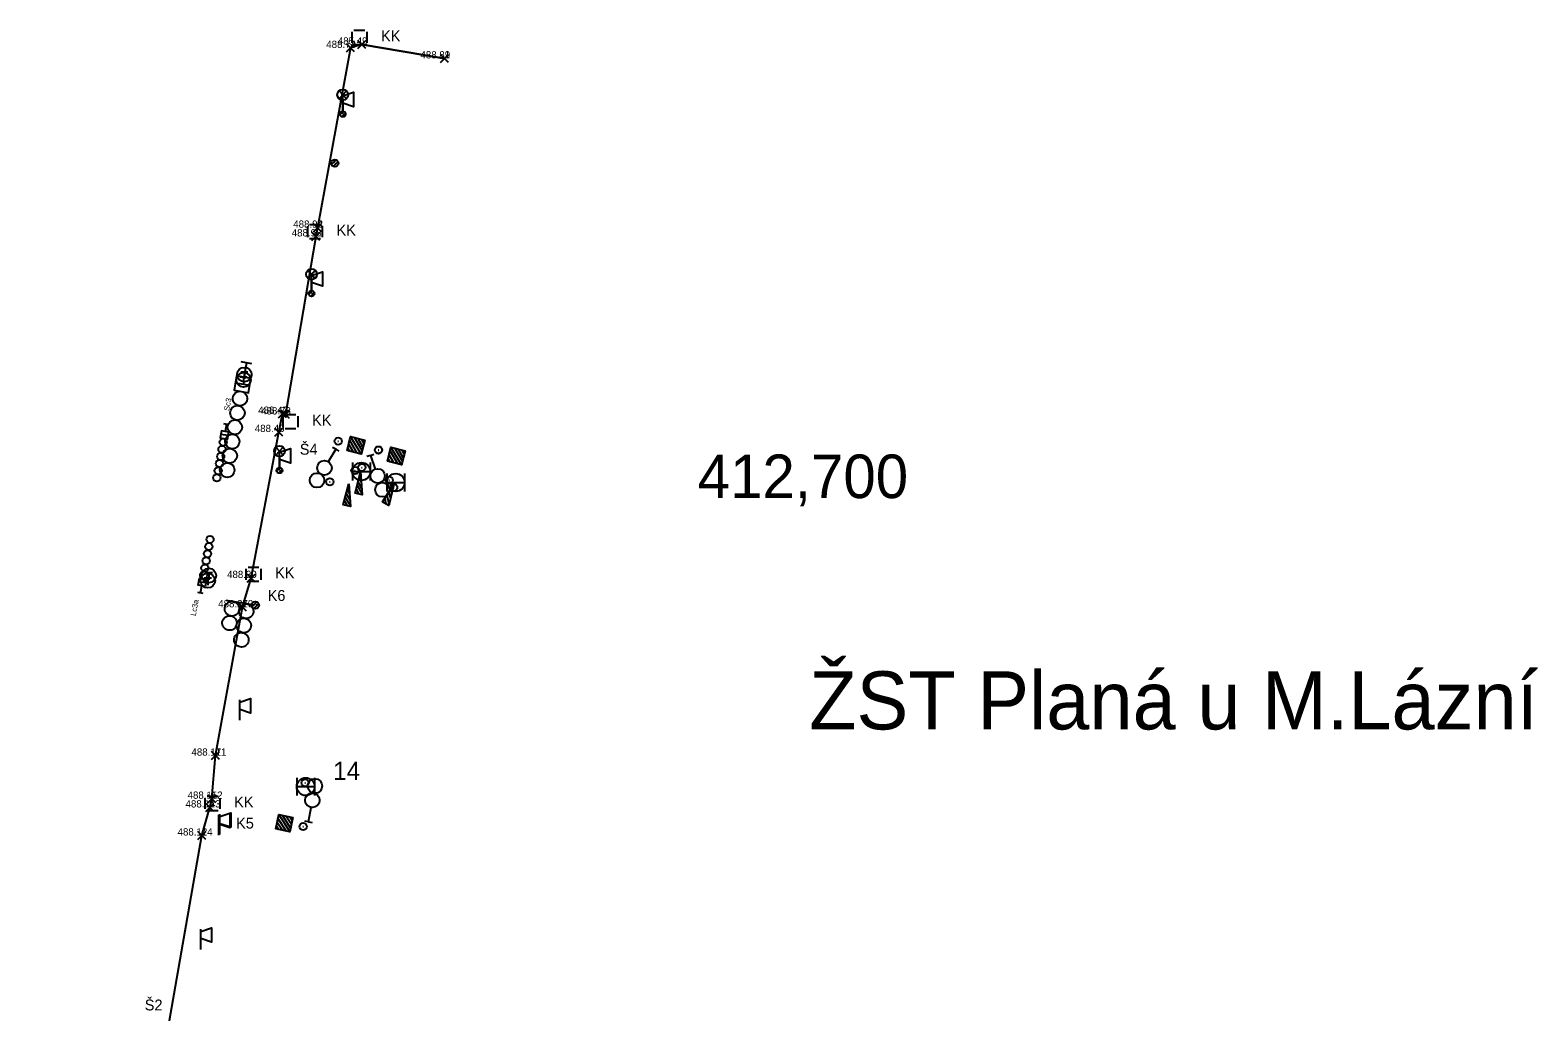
# Model space of a CAD drawing. Extents: x -874058 to -854960, y -10531873 to -1049126.
# Drawn here: x -866509.5 to -866301.7, y -1050024 to -1049888.8 of the extents above; entities that cross this region are included whole.
import ezdxf

# ---------------------------------------------------------------- set-up
doc = ezdxf.new("R2010")
doc.units = 0
for name, color, linetype in [('PS 63-21-01_Návěstidla', 7, 'Continuous'), ('PS 63-21-01_Názvy_náv', 7, 'Continuous'), ('SO_63-33-21_pedestrail', 7, 'Continuous'), ('Vrstva 2', 7, 'Continuous'), ('Vrstva 23', 7, 'Continuous'), ('Vrstva 25', 7, 'Continuous'), ('Vrstva 3', 7, 'Continuous'), ('Vrstva 31', 7, 'Continuous'), ('Vrstva 32', 7, 'Continuous'), ('Vrstva 33', 7, 'Continuous'), ('Vrstva 35', 7, 'Continuous'), ('Vrstva 36', 7, 'Continuous'), ('Vrstva 50', 7, 'Continuous'), ('Vrstva 6', 7, 'Continuous'), ('Vrstva 60', 7, 'Continuous'), ('Vrstva 61', 7, 'Continuous'), ('Vrstva 7', 7, 'Continuous')]:
    doc.layers.add(name, color=color, linetype=linetype)

msp = doc.modelspace()

# ---------------------------------------------------------------- linework, layer by layer
at = {"layer": 'PS 63-21-01_Návěstidla'}
for p, q in [((-866482.23, -1049944.59), (-866483.21, -1049944.42)), ((-866482.23, -1049944.59), (-866483.21, -1049944.42)), ((-866482.09, -1049943.1), (-866482.82, -1049942.96)), ((-866482.09, -1049943.1), (-866482.82, -1049942.96)), ((-866482.45, -1049943.03), (-866482.45, -1049943.03)), ((-866482.45, -1049943.03), (-866482.45, -1049943.03)), ((-866485.28, -1049964.89), (-866486.27, -1049964.71)), ((-866485.28, -1049964.89), (-866486.27, -1049964.71)), ((-866485.67, -1049966.34), (-866486.41, -1049966.21)), ((-866485.67, -1049966.34), (-866486.41, -1049966.21)), ((-866486.04, -1049966.27), (-866486.04, -1049966.27)), ((-866486.04, -1049966.27), (-866486.04, -1049966.27))]:
    msp.add_line(p, q, dxfattribs=at)
for points in [[(-866482.45, -1049943.03), (-866482.63, -1049944.01), (-866483.12, -1049943.93), (-866483.3, -1049944.91), (-866482.32, -1049945.09), (-866482.14, -1049944.1), (-866482.63, -1049944.01)], [(-866482.45, -1049943.03), (-866482.63, -1049944.01), (-866483.12, -1049943.93), (-866483.3, -1049944.91), (-866482.32, -1049945.09), (-866482.14, -1049944.1), (-866482.63, -1049944.01)], [(-866486.04, -1049966.27), (-866485.86, -1049965.29), (-866486.36, -1049965.2), (-866486.18, -1049964.22), (-866485.2, -1049964.39), (-866485.37, -1049965.38), (-866485.86, -1049965.29)], [(-866486.04, -1049966.27), (-866485.86, -1049965.29), (-866486.36, -1049965.2), (-866486.18, -1049964.22), (-866485.2, -1049964.39), (-866485.37, -1049965.38), (-866485.86, -1049965.29)]]:
    msp.add_lwpolyline(points, dxfattribs=at)
for centre in [(-866483.07, -1049946.48), (-866483.07, -1049946.48), (-866482.9, -1049945.49), (-866482.9, -1049945.49), (-866483.42, -1049948.44), (-866483.42, -1049948.44), (-866483.25, -1049947.46), (-866483.25, -1049947.46), (-866483.78, -1049950.41), (-866483.78, -1049950.41), (-866483.6, -1049949.43), (-866483.6, -1049949.43), (-866484.72, -1049958.89), (-866484.72, -1049958.89), (-866485.07, -1049960.86), (-866485.07, -1049960.86), (-866484.89, -1049959.88), (-866484.89, -1049959.88), (-866485.42, -1049962.83), (-866485.42, -1049962.83), (-866485.25, -1049961.84), (-866485.25, -1049961.84), (-866485.6, -1049963.81), (-866485.6, -1049963.81)]:
    msp.add_circle(centre, 0.5, dxfattribs=at)
at = {"layer": 'Vrstva 25'}
for p, q in [((-866466.92, -1049897.09), (-866465.93, -1049898.21)), ((-866466.91, -1049898.22), (-866465.93, -1049897.1)), ((-866466.43, -1049898.4), (-866466.43, -1049899.9)), ((-866466.82, -1049900.38), (-866466.35, -1049899.91)), ((-866466.55, -1049900.68), (-866466.05, -1049900.18)), ((-866471.22, -1049921.81), (-866470.23, -1049922.93)), ((-866471.21, -1049922.94), (-866470.22, -1049921.82)), ((-866470.73, -1049923.12), (-866470.73, -1049924.62)), ((-866471.12, -1049925.1), (-866470.65, -1049924.63)), ((-866470.85, -1049925.4), (-866470.35, -1049924.9)), ((-866475.64, -1049946.17), (-866474.65, -1049947.28)), ((-866475.63, -1049947.3), (-866474.65, -1049946.18)), ((-866475.15, -1049947.48), (-866475.15, -1049948.98)), ((-866475.54, -1049949.46), (-866475.07, -1049948.99)), ((-866475.27, -1049949.76), (-866474.77, -1049949.26))]:
    msp.add_line(p, q, dxfattribs=at)
for centre, radius in [((-866466.43, -1049897.65), 0.749), ((-866466.43, -1049900.3), 0.4), ((-866466.43, -1049900.3), 0.4), ((-866470.73, -1049922.37), 0.749), ((-866470.73, -1049925.02), 0.4), ((-866470.73, -1049925.02), 0.4), ((-866475.15, -1049946.73), 0.749), ((-866475.15, -1049949.38), 0.4), ((-866475.15, -1049949.38), 0.4)]:
    msp.add_circle(centre, radius, dxfattribs=at)
at = {"layer": 'Vrstva 3'}
for p, q in [((-866480.49, -1049935.79), (-866479.49, -1049935.79)), ((-866479.99, -1049935.79), (-866479.99, -1049936.79)), ((-866480.59, -1049936.51), (-866479.59, -1049936.51)), ((-866480.09, -1049936.51), (-866480.09, -1049937.51)), ((-866465.44, -1049946.76), (-866465.74, -1049946.26)), ((-866464.93, -1049946.89), (-866465.61, -1049945.75)), ((-866464.42, -1049947.03), (-866465.47, -1049945.24)), ((-866463.9, -1049947.16), (-866465.34, -1049944.72)), ((-866463.77, -1049946.65), (-866464.83, -1049944.85)), ((-866463.64, -1049946.13), (-866464.31, -1049944.99)), ((-866463.51, -1049945.62), (-866463.8, -1049945.12)), ((-866458.34, -1049948.63), (-866459.78, -1049946.19)), ((-866458.21, -1049948.12), (-866459.27, -1049946.32)), ((-866458.08, -1049947.6), (-866458.75, -1049946.46)), ((-866465.09, -1049948.31), (-866465.09, -1049950.77)), ((-866462.63, -1049948.31), (-866462.63, -1049950.77)), ((-866459.88, -1049948.23), (-866460.18, -1049947.73)), ((-866459.37, -1049948.36), (-866460.05, -1049947.22)), ((-866458.86, -1049948.5), (-866459.91, -1049946.71)), ((-866457.95, -1049947.09), (-866458.24, -1049946.59)), ((-866465.09, -1049949.54), (-866462.63, -1049949.54)), ((-866464.2, -1049950.44), (-866463.88, -1049950.97)), ((-866464.06, -1049949.93), (-866463.94, -1049950.14)), ((-866460.36, -1049949.82), (-866460.36, -1049952.28)), ((-866457.9, -1049949.82), (-866457.9, -1049952.28)), ((-866465.94, -1049952.57), (-866465.44, -1049953.42)), ((-866465.81, -1049952.06), (-866465.5, -1049952.58)), ((-866465.67, -1049951.54), (-866465.55, -1049951.75)), ((-866464.73, -1049952.49), (-866464.72, -1049952.51)), ((-866464.6, -1049951.98), (-866464.21, -1049952.64)), ((-866464.46, -1049951.47), (-866463.77, -1049952.64)), ((-866464.33, -1049950.95), (-866463.83, -1049951.81)), ((-866460.36, -1049951.05), (-866457.9, -1049951.05)), ((-866460.36, -1049952.79), (-866460.05, -1049954.12)), ((-866460.08, -1049952.34), (-866459.86, -1049953.3)), ((-866459.8, -1049951.89), (-866459.66, -1049952.49)), ((-866459.52, -1049951.44), (-866459.47, -1049951.67)), ((-866466.34, -1049954.11), (-866466.34, -1049954.12)), ((-866466.21, -1049953.59), (-866465.82, -1049954.25)), ((-866466.08, -1049953.08), (-866465.39, -1049954.26)), ((-866460.92, -1049953.69), (-866460.92, -1049953.7)), ((-866460.64, -1049953.24), (-866460.47, -1049953.99)), ((-866485.53, -1049964.17), (-866484.53, -1049964.17)), ((-866485.38, -1049963.46), (-866484.38, -1049963.46)), ((-866485.03, -1049964.17), (-866485.03, -1049965.17)), ((-866484.88, -1049963.46), (-866484.88, -1049964.46)), ((-866472.76, -1049991.71), (-866472.76, -1049994.17)), ((-866470.3, -1049991.71), (-866470.3, -1049994.17)), ((-866472.76, -1049992.94), (-866470.3, -1049992.94)), ((-866475.59, -1049998.35), (-866475.27, -1049998.83)), ((-866475.48, -1049997.83), (-866474.75, -1049998.94)), ((-866475.37, -1049997.31), (-866474.23, -1049999.05)), ((-866475.26, -1049996.79), (-866473.71, -1049999.16)), ((-866474.75, -1049996.9), (-866473.61, -1049998.64)), ((-866474.23, -1049997.01), (-866473.5, -1049998.12)), ((-866473.71, -1049997.12), (-866473.39, -1049997.6))]:
    msp.add_line(p, q, dxfattribs=at)
for points in [[(-866465.84, -1049946.66), (-866465.34, -1049944.72), (-866463.4, -1049945.22), (-866463.9, -1049947.16)], [(-866465.84, -1049946.66), (-866465.34, -1049944.72), (-866463.4, -1049945.22), (-866463.9, -1049947.16)], [(-866460.28, -1049948.13), (-866459.78, -1049946.19), (-866457.84, -1049946.69), (-866458.34, -1049948.63)], [(-866460.28, -1049948.13), (-866459.78, -1049946.19), (-866457.84, -1049946.69), (-866458.34, -1049948.63)], [(-866473.31, -1049997.2), (-866473.71, -1049999.16), (-866475.67, -1049998.75), (-866475.26, -1049996.79)], [(-866473.31, -1049997.2), (-866473.71, -1049999.16), (-866475.67, -1049998.75), (-866475.26, -1049996.79)]]:
    msp.add_lwpolyline(points, close=True, dxfattribs=at)
for points in [[(-866465.84, -1049946.66), (-866465.34, -1049944.72), (-866463.4, -1049945.22), (-866463.9, -1049947.16), (-866465.84, -1049946.66)], [(-866465.84, -1049946.66), (-866465.34, -1049944.72), (-866463.4, -1049945.22), (-866463.9, -1049947.16), (-866465.84, -1049946.66)], [(-866460.28, -1049948.13), (-866459.78, -1049946.19), (-866457.84, -1049946.69), (-866458.34, -1049948.63), (-866460.28, -1049948.13)], [(-866460.28, -1049948.13), (-866459.78, -1049946.19), (-866457.84, -1049946.69), (-866458.34, -1049948.63), (-866460.28, -1049948.13)], [(-866463.98, -1049949.6), (-866463.77, -1049952.76), (-866464.73, -1049952.5), (-866463.98, -1049949.6)], [(-866463.98, -1049949.6), (-866463.77, -1049952.76), (-866464.73, -1049952.5), (-866463.98, -1049949.6)], [(-866465.59, -1049951.22), (-866465.38, -1049954.37), (-866466.35, -1049954.12), (-866465.59, -1049951.22)], [(-866465.59, -1049951.22), (-866465.38, -1049954.37), (-866466.35, -1049954.12), (-866465.59, -1049951.22)], [(-866459.34, -1049951.15), (-866460.08, -1049954.23), (-866460.93, -1049953.7), (-866459.34, -1049951.15)], [(-866459.34, -1049951.15), (-866460.08, -1049954.23), (-866460.93, -1049953.7), (-866459.34, -1049951.15)], [(-866473.31, -1049997.2), (-866473.71, -1049999.16), (-866475.67, -1049998.75), (-866475.26, -1049996.79), (-866473.31, -1049997.2)], [(-866473.31, -1049997.2), (-866473.71, -1049999.16), (-866475.67, -1049998.75), (-866475.26, -1049996.79), (-866473.31, -1049997.2)]]:
    msp.add_lwpolyline(points, dxfattribs=at)
for centre, radius in [((-866480.09, -1049936.91), 1), ((-866479.99, -1049936.19), 1), ((-866463.86, -1049949.54), 1.23), ((-866459.13, -1049951.05), 1.23), ((-866484.88, -1049963.86), 1), ((-866485.03, -1049964.57), 1), ((-866471.53, -1049992.94), 1.23)]:
    msp.add_circle(centre, radius, dxfattribs=at)
at = {"layer": 'Vrstva 32'}
msp.add_line((-866470.13, -1049917.16), (-866474.34, -1049941.68), dxfattribs=at)
for points in [[(-866465.37, -1049891.2), (-866469.92, -1049915.96), (-866470.13, -1049917.16)], [(-866452.39, -1049892.64), (-866463.78, -1049890.74), (-866465.37, -1049891.2)], [(-866467.53, -1049907.06), (-866467.46, -1049907.09)], [(-866467.53, -1049907.06), (-866467.46, -1049907.09)], [(-866509.51, -1050138.6), (-866508.38, -1050128.3), (-866506.21, -1050113.94), (-866501.87, -1050089.49), (-866497.28, -1050066.11), (-866497.1, -1050064.94), (-866497.46, -1050061.87), (-866494.3, -1050044.44), (-866492.93, -1050041.88), (-866492.72, -1050040.74), (-866490.75, -1050027.82), (-866490.32, -1050025.14), (-866485.86, -1049999.67), (-866484.76, -1049995.81), (-866484.48, -1049994.61), (-866483.95, -1049988.67), (-866480.26, -1049968.24), (-866479.04, -1049964.21), (-866475.22, -1049944.1), (-866474.75, -1049941.59)], [(-866478.26, -1049967.83), (-866478.4, -1049967.95)], [(-866478.26, -1049967.83), (-866478.4, -1049967.95)]]:
    msp.add_lwpolyline(points, dxfattribs=at)
at = {"layer": 'Vrstva 33'}
for p, q in [((-866466.43, -1049900.3), (-866466.43, -1049897.5)), ((-866470.73, -1049925.02), (-866470.73, -1049922.22)), ((-866475.15, -1049949.38), (-866475.15, -1049946.58)), ((-866480.63, -1049983.8), (-866480.63, -1049981)), ((-866483.5, -1049999.6), (-866483.5, -1049996.8)), ((-866483.36, -1049999.54), (-866483.36, -1049996.74)), ((-866486.01, -1050015.37), (-866486.01, -1050012.57))]:
    msp.add_line(p, q, dxfattribs=at)
for points in [[(-866466.43, -1049897.8), (-866464.93, -1049897.3), (-866464.93, -1049899.3), (-866466.43, -1049898.8)], [(-866470.73, -1049922.52), (-866469.23, -1049922.02), (-866469.23, -1049924.02), (-866470.73, -1049923.52)], [(-866475.15, -1049946.88), (-866473.65, -1049946.38), (-866473.65, -1049948.38), (-866475.15, -1049947.88)], [(-866480.63, -1049981.3), (-866479.13, -1049980.8), (-866479.13, -1049982.8), (-866480.63, -1049982.3)], [(-866483.5, -1049997.1), (-866482, -1049996.6), (-866482, -1049998.6), (-866483.5, -1049998.1)], [(-866483.36, -1049997.04), (-866481.86, -1049996.54), (-866481.86, -1049998.54), (-866483.36, -1049998.04)], [(-866486.01, -1050012.87), (-866484.51, -1050012.37), (-866484.51, -1050014.37), (-866486.01, -1050013.87)]]:
    msp.add_lwpolyline(points, dxfattribs=at)
at = {"layer": 'Vrstva 35'}
for p, q in [((-866465.13, -1049890.5), (-866465.13, -1049889)), ((-866465.13, -1049890.5), (-866465.13, -1049889)), ((-866464.88, -1049888.75), (-866463.38, -1049888.75)), ((-866464.88, -1049888.75), (-866463.38, -1049888.75)), ((-866463.13, -1049889), (-866463.13, -1049890.5)), ((-866463.13, -1049889), (-866463.13, -1049890.5)), ((-866463.38, -1049890.75), (-866464.88, -1049890.75)), ((-866463.38, -1049890.75), (-866464.88, -1049890.75)), ((-866463.78, -1049890.74), (-866452.39, -1049892.64)), ((-866471.26, -1049917.25), (-866471.26, -1049915.75)), ((-866471.26, -1049917.25), (-866471.26, -1049915.75)), ((-866471.01, -1049915.5), (-866469.51, -1049915.5)), ((-866471.01, -1049915.5), (-866469.51, -1049915.5)), ((-866469.26, -1049915.75), (-866469.26, -1049917.25)), ((-866469.26, -1049915.75), (-866469.26, -1049917.25)), ((-866469.51, -1049917.5), (-866471.01, -1049917.5)), ((-866469.51, -1049917.5), (-866471.01, -1049917.5)), ((-866474.63, -1049943.42), (-866474.63, -1049941.92)), ((-866474.63, -1049943.42), (-866474.63, -1049941.92)), ((-866474.38, -1049941.67), (-866472.88, -1049941.67)), ((-866474.38, -1049941.67), (-866472.88, -1049941.67)), ((-866472.63, -1049941.92), (-866472.63, -1049943.42)), ((-866472.63, -1049941.92), (-866472.63, -1049943.42)), ((-866472.88, -1049943.67), (-866474.38, -1049943.67)), ((-866472.88, -1049943.67), (-866474.38, -1049943.67)), ((-866479.73, -1049964.44), (-866479.73, -1049962.94)), ((-866479.73, -1049964.44), (-866479.73, -1049962.94)), ((-866479.48, -1049962.69), (-866477.98, -1049962.69)), ((-866479.48, -1049962.69), (-866477.98, -1049962.69)), ((-866477.73, -1049962.94), (-866477.73, -1049964.44)), ((-866477.73, -1049962.94), (-866477.73, -1049964.44)), ((-866477.98, -1049964.69), (-866479.48, -1049964.69)), ((-866477.98, -1049964.69), (-866479.48, -1049964.69)), ((-866485.12, -1049994.26), (-866483.62, -1049994.26)), ((-866485.12, -1049994.26), (-866483.62, -1049994.26)), ((-866485.37, -1049996.01), (-866485.37, -1049994.51)), ((-866485.37, -1049996.01), (-866485.37, -1049994.51)), ((-866483.62, -1049996.26), (-866485.12, -1049996.26)), ((-866483.62, -1049996.26), (-866485.12, -1049996.26)), ((-866483.37, -1049994.51), (-866483.37, -1049996.01)), ((-866483.37, -1049994.51), (-866483.37, -1049996.01))]:
    msp.add_line(p, q, dxfattribs=at)
at = {"layer": 'Vrstva 36'}
for p, q in [((-866467.99, -1049907.24), (-866467.34, -1049906.6)), ((-866467.73, -1049907.51), (-866467.08, -1049906.86)), ((-866478.93, -1049968.12), (-866478.29, -1049967.48)), ((-866478.67, -1049968.39), (-866478.02, -1049967.74))]:
    msp.add_line(p, q, dxfattribs=at)
for centre in [(-866467.53, -1049907.06), (-866478.47, -1049967.94)]:
    msp.add_circle(centre, 0.5, dxfattribs=at)
at = {"layer": 'Vrstva 50'}
for p, q in [((-866467.1, -1049945.36), (-866467, -1049945.36)), ((-866461.57, -1049946.58), (-866461.47, -1049946.58)), ((-866461.55, -1049946.57), (-866461.45, -1049946.57)), ((-866464.8, -1049949.4), (-866464.7, -1049949.4)), ((-866463.86, -1049948.97), (-866463.76, -1049948.97)), ((-866460.07, -1049950.73), (-866459.97, -1049950.73)), ((-866459.46, -1049951.73), (-866459.36, -1049951.73)), ((-866471.67, -1049992.42), (-866471.57, -1049992.42)), ((-866471.94, -1049998.44), (-866471.84, -1049998.44))]:
    msp.add_line(p, q, dxfattribs=at)
for centre in [(-866467.05, -1049945.36), (-866461.52, -1049946.58), (-866461.5, -1049946.57), (-866463.81, -1049948.97), (-866464.75, -1049949.4), (-866460.02, -1049950.73), (-866459.41, -1049951.73), (-866471.62, -1049992.42), (-866471.89, -1049998.44)]:
    msp.add_circle(centre, 0.5, dxfattribs=at)
at = {"layer": 'Vrstva 6'}
for p, q in [((-866478.97, -1049934.7), (-866480.45, -1049934.44)), ((-866479.71, -1049934.57), (-866479.71, -1049934.57)), ((-866479.25, -1049937.7), (-866481.22, -1049937.35)), ((-866467.4, -1049946.47), (-866468.43, -1049948.18)), ((-866467.4, -1049946.47), (-866467.83, -1049946.21)), ((-866467.4, -1049946.47), (-866466.97, -1049946.73)), ((-866462.62, -1049947.32), (-866463.09, -1049947.49)), ((-866462.62, -1049947.32), (-866462.15, -1049947.15)), ((-866462.62, -1049947.32), (-866461.95, -1049949.21)), ((-866480.54, -1049967.62), (-866482.51, -1049967.28)), ((-866478.57, -1049967.96), (-866480.54, -1049967.62)), ((-866471.15, -1049997.77), (-866470.8, -1049995.8)), ((-866471.15, -1049997.77), (-866471.64, -1049997.68)), ((-866471.15, -1049997.77), (-866470.66, -1049997.86))]:
    msp.add_line(p, q, dxfattribs=at)
msp.add_lwpolyline([(-866479.71, -1049934.57), (-866480.06, -1049936.54), (-866481.05, -1049936.36), (-866481.4, -1049938.33), (-866479.43, -1049938.68), (-866479.08, -1049936.71), (-866480.06, -1049936.54)], dxfattribs=at)
for centre in [(-866480.59, -1049939.49), (-866480.94, -1049941.46), (-866481.65, -1049945.4), (-866481.3, -1049943.43), (-866482, -1049947.37), (-866482.35, -1049949.34), (-866468.95, -1049949.04), (-866469.98, -1049950.75), (-866461.62, -1049950.15), (-866460.96, -1049952.04), (-866470.27, -1049992.85), (-866470.62, -1049994.82)]:
    msp.add_circle(centre, 1, dxfattribs=at)
for centre in [(-866481.7, -1049968.44), (-866482.04, -1049970.41), (-866479.73, -1049968.78), (-866480.06, -1049970.75), (-866480.4, -1049972.72)]:
    msp.add_ellipse(centre, major_axis=(-0.17, -0.986), ratio=0.999505, dxfattribs=at)
at = {"layer": 'Vrstva 60'}
for p, q in [((-866464.33, -1049891.29), (-866463.23, -1049890.19)), ((-866463.23, -1049891.29), (-866464.33, -1049890.19)), ((-866465.92, -1049891.75), (-866464.82, -1049890.65)), ((-866464.82, -1049891.75), (-866465.92, -1049890.65)), ((-866452.94, -1049893.19), (-866451.84, -1049892.09)), ((-866451.84, -1049893.19), (-866452.94, -1049892.09)), ((-866470.47, -1049916.51), (-866469.37, -1049915.41)), ((-866469.37, -1049916.51), (-866470.47, -1049915.41)), ((-866470.68, -1049917.71), (-866469.58, -1049916.61)), ((-866469.58, -1049917.71), (-866470.68, -1049916.61)), ((-866475.3, -1049942.14), (-866474.2, -1049941.04)), ((-866474.2, -1049942.14), (-866475.3, -1049941.04)), ((-866474.89, -1049942.23), (-866473.79, -1049941.13)), ((-866473.79, -1049942.23), (-866474.89, -1049941.13)), ((-866475.77, -1049944.65), (-866474.67, -1049943.55)), ((-866474.67, -1049944.65), (-866475.77, -1049943.55)), ((-866479.59, -1049964.76), (-866478.49, -1049963.66)), ((-866478.49, -1049964.76), (-866479.59, -1049963.66)), ((-866480.81, -1049968.79), (-866479.71, -1049967.69)), ((-866479.71, -1049968.79), (-866480.81, -1049967.69)), ((-866484.5, -1049989.22), (-866483.4, -1049988.12)), ((-866483.4, -1049989.22), (-866484.5, -1049988.12)), ((-866485.03, -1049995.16), (-866483.93, -1049994.06)), ((-866483.93, -1049995.16), (-866485.03, -1049994.06)), ((-866485.31, -1049996.36), (-866484.21, -1049995.26)), ((-866484.21, -1049996.36), (-866485.31, -1049995.26)), ((-866486.41, -1050000.22), (-866485.31, -1049999.12)), ((-866485.31, -1050000.22), (-866486.41, -1049999.12))]:
    msp.add_line(p, q, dxfattribs=at)
at = {"layer": 'Vrstva 7'}
msp.add_line((-866468.26, -1049950.95), (-866468.16, -1049950.95), dxfattribs=at)
msp.add_circle((-866468.21, -1049950.95), 0.5, dxfattribs=at)

# ---------------------------------------------------------------- texts
at = {"layer": 'PS 63-21-01_Názvy_náv'}
msp.add_text('Lc3a', height=0.75, rotation=80.2727, dxfattribs=at).set_placement((-866486.68, -1049969.47))
msp.add_text('Lc3a', height=0.75, rotation=80.2727, dxfattribs=at).set_placement((-866486.68, -1049969.47))
at = {"layer": 'SO_63-33-21_pedestrail'}
msp.add_text('Sc3', height=0.75, rotation=79.3956, dxfattribs=at).set_placement((-866482.08, -1049941.23))
msp.add_text('Sc3', height=0.75, rotation=79.3956, dxfattribs=at).set_placement((-866482.08, -1049941.23))
at = {"layer": 'Vrstva 2'}
msp.add_text('14', height=2.5, dxfattribs=at).set_placement((-866467.75, -1049992.01))
at = {"layer": 'Vrstva 23'}
msp.add_text('ŽST Planá u M.Lázní', height=8, dxfattribs=at).set_placement((-866402.16, -1049985.06))
msp.add_text('ŽST Planá u M.Lázní', height=8, dxfattribs=at).set_placement((-866402.16, -1049985.06))
at = {"layer": 'Vrstva 31'}
for s, p in [('Š4', (-866472.35, -1049947.22)), ('K6', (-866476.78, -1049967.36)), ('K5', (-866481.13, -1049998.72)), ('Š2', (-866493.72, -1050023.76))]:
    msp.add_text(s, height=1.5, dxfattribs=at).set_placement(p)
at = {"layer": 'Vrstva 35'}
for p in [(-866461.16, -1049890.29), (-866467.29, -1049917.04), (-866470.66, -1049943.21), (-866475.76, -1049964.23), (-866481.4, -1049995.8)]:
    msp.add_text('KK', height=1.5, dxfattribs=at).set_placement(p)
at = {"layer": 'Vrstva 60'}
for s, p in [('3', (-866465.37, -1049891.2)), ('2', (-866463.78, -1049890.74)), ('1', (-866452.39, -1049892.64)), ('4', (-866469.92, -1049915.96)), ('5', (-866470.13, -1049917.16)), ('7', (-866474.75, -1049941.59)), ('6', (-866474.34, -1049941.68)), ('8', (-866475.22, -1049944.1)), ('9', (-866479.04, -1049964.21)), ('10', (-866480.26, -1049968.24)), ('11', (-866483.95, -1049988.67)), ('12', (-866484.48, -1049994.61)), ('13', (-866484.76, -1049995.81)), ('14', (-866485.86, -1049999.67))]:
    msp.add_text(s, height=1, dxfattribs=at).set_placement(p)
at = {"layer": 'Vrstva 61'}
for s, p in [('488.74 ', (-866468.7, -1049891.2)), ('485.49 ', (-866467.11, -1049890.74)), ('488.89 ', (-866455.72, -1049892.64)), ('488.92 ', (-866473.25, -1049915.96)), ('488.92 ', (-866473.46, -1049917.16)), ('488.42 ', (-866478.08, -1049941.59)), ('488.73 ', (-866477.67, -1049941.68)), ('488.40 ', (-866478.55, -1049944.1)), ('488.30 ', (-866482.37, -1049964.21)), ('488.27 ', (-866483.59, -1049968.24)), ('488.17 ', (-866487.28, -1049988.67)), ('488.15 ', (-866487.81, -1049994.61)), ('488.14 ', (-866488.09, -1049995.81)), ('488.12 ', (-866489.19, -1049999.67))]:
    msp.add_text(s, height=1, dxfattribs=at).set_placement(p)
at = {"layer": 'Vrstva 7'}
msp.add_text('412,700', height=6, dxfattribs=at).set_placement((-866417.51, -1049953.2))

doc.saveas('drawing.dxf')
